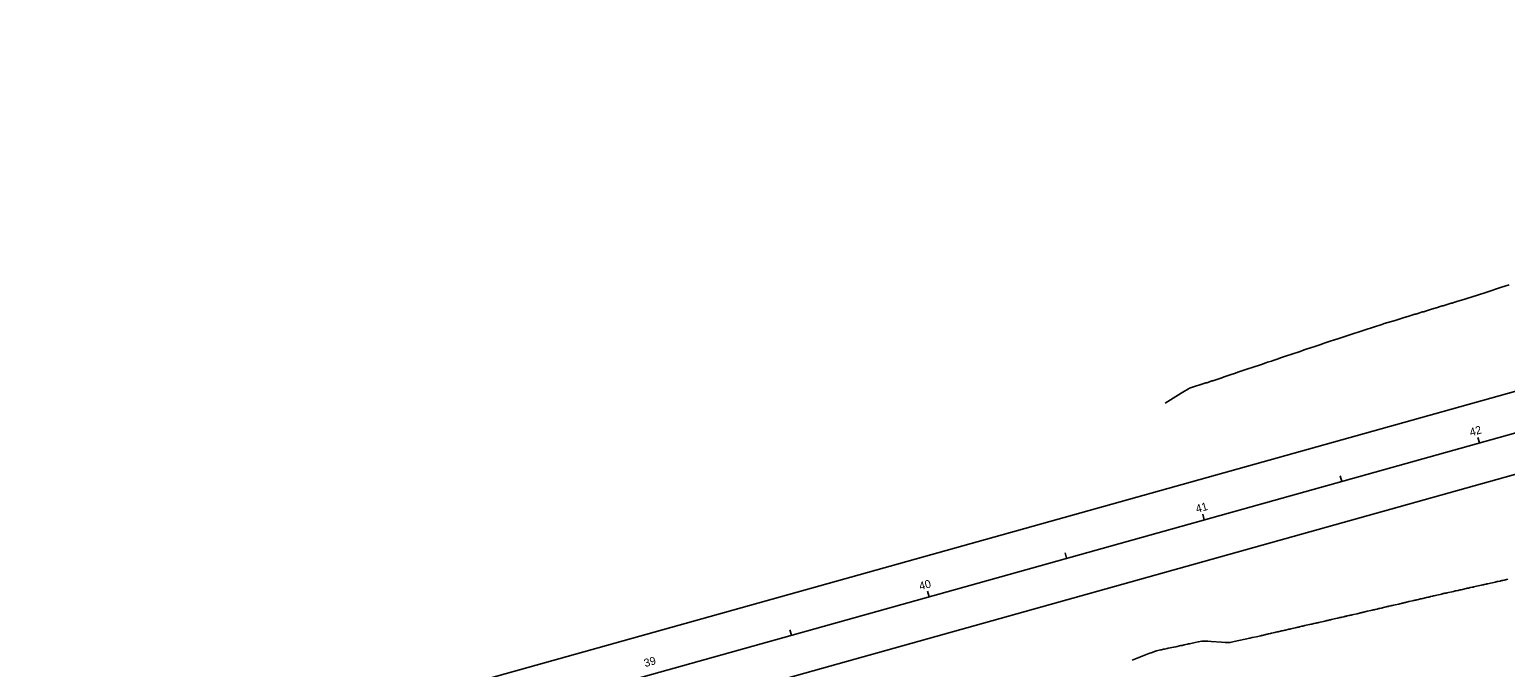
# Model space of a CAD drawing. Extents: x 1512289 to 1544686, y 552531 to 589211.
# Drawn here: x 1542314 to 1542831, y 587195 to 587419 of the extents above; entities that cross this region are included whole.
import ezdxf

# ---------------------------------------------------------------- set-up
doc = ezdxf.new("R2010")
doc.units = 0
for name, color, linetype in [('DR_X_Flood_Boundary', 7, 'Continuous'), ('DR_X_Underdrain', 7, 'Continuous'), ('GE_X_CL_20', 7, 'Continuous'), ('GK_Visualization', 7, 'Continuous')]:
    doc.layers.add(name, color=color, linetype=linetype)

msp = doc.modelspace()

# ---------------------------------------------------------------- linework, layer by layer
at = {"layer": 'DR_X_Flood_Boundary'}
for points in [[(1542711.77, 587287.84), (1542717.39, 587291.34), (1542718.47, 587292), (1542719.31, 587292.5), (1542719.91, 587292.83), (1542720.27, 587292.99), (1542726.04, 587294.85), (1542726.39, 587294.96), (1542726.71, 587295.07), (1542728.08, 587295.55), (1542728.4, 587295.66), (1542728.75, 587295.77), (1542730.52, 587296.35), (1542730.88, 587296.47), (1542731.23, 587296.59), (1542732.76, 587297.12), (1542733.11, 587297.24), (1542733.47, 587297.36), (1542735.26, 587297.94), (1542735.63, 587298.06), (1542735.97, 587298.18), (1542737.5, 587298.71), (1542737.84, 587298.83), (1542738.21, 587298.95), (1542740.01, 587299.53), (1542740.38, 587299.65), (1542740.72, 587299.77), (1542742.23, 587300.29), (1542742.58, 587300.41), (1542742.94, 587300.53), (1542744.76, 587301.12), (1542745.12, 587301.24), (1542745.47, 587301.36), (1542746.95, 587301.87), (1542747.56, 587302.08), (1542748.91, 587302.52), (1542749.52, 587302.72), (1542750.98, 587303.24), (1542751.33, 587303.35), (1542752.08, 587303.6), (1542753.54, 587304.07), (1542754.24, 587304.31), (1542755.71, 587304.82), (1542756.05, 587304.94), (1542756.81, 587305.19), (1542758.28, 587305.67), (1542758.98, 587305.9), (1542760.44, 587306.41), (1542761.15, 587306.65), (1542763.02, 587307.26), (1542763.73, 587307.49), (1542765.16, 587307.99), (1542765.88, 587308.23), (1542767.76, 587308.85), (1542768.47, 587309.08), (1542769.89, 587309.58), (1542770.61, 587309.82), (1542772.5, 587310.43), (1542773.21, 587310.67), (1542774.62, 587311.16), (1542775.33, 587311.4), (1542781.72, 587313.47), (1542787.57, 587315.37), (1542788.13, 587315.55), (1542788.4, 587315.63), (1542792.22, 587316.75), (1542792.6, 587316.87), (1542792.94, 587316.97), (1542793.24, 587317.07), (1542794.01, 587317.32), (1542794.31, 587317.41), (1542794.65, 587317.52), (1542795.03, 587317.63), (1542797.03, 587318.22), (1542797.41, 587318.34), (1542797.75, 587318.44), (1542798.05, 587318.54), (1542798.8, 587318.78), (1542799.1, 587318.87), (1542799.44, 587318.98), (1542799.82, 587319.09), (1542801.84, 587319.69), (1542802.22, 587319.8), (1542802.56, 587319.91), (1542802.85, 587320), (1542803.59, 587320.24), (1542803.88, 587320.33), (1542804.22, 587320.44), (1542804.61, 587320.55), (1542806.65, 587321.15), (1542807.03, 587321.27), (1542807.36, 587321.37), (1542807.66, 587321.46), (1542808.38, 587321.7), (1542808.67, 587321.79), (1542809.01, 587321.89), (1542809.4, 587322.01), (1542811.46, 587322.62), (1542811.84, 587322.73), (1542812.17, 587322.83), (1542812.46, 587322.92), (1542813.17, 587323.15), (1542813.46, 587323.25), (1542813.8, 587323.35), (1542814.18, 587323.46), (1542816.27, 587324.08), (1542816.65, 587324.19), (1542816.98, 587324.29), (1542817.27, 587324.38), (1542821.08, 587325.62), (1542824.33, 587326.67), (1542829.08, 587328.21), (1542832.15, 587329.2)], [(1542831.68, 587226.17), (1542830.42, 587225.89), (1542829.98, 587225.79), (1542829.59, 587225.7), (1542829.25, 587225.63), (1542828.96, 587225.56), (1542828.27, 587225.42), (1542827.98, 587225.35), (1542827.64, 587225.28), (1542827.25, 587225.19), (1542826.8, 587225.09), (1542825.55, 587224.8), (1542825.1, 587224.7), (1542824.71, 587224.62), (1542824.37, 587224.54), (1542824.08, 587224.48), (1542823.39, 587224.33), (1542823.1, 587224.27), (1542822.76, 587224.2), (1542822.37, 587224.11), (1542821.93, 587224.01), (1542820.67, 587223.72), (1542820.22, 587223.62), (1542819.83, 587223.53), (1542819.49, 587223.46), (1542819.21, 587223.39), (1542818.52, 587223.25), (1542818.23, 587223.19), (1542817.89, 587223.11), (1542817.5, 587223.02), (1542817.05, 587222.92), (1542815.79, 587222.64), (1542815.35, 587222.53), (1542814.96, 587222.45), (1542814.62, 587222.37), (1542814.33, 587222.31), (1542813.64, 587222.16), (1542813.35, 587222.1), (1542813.02, 587222.03), (1542812.62, 587221.94), (1542812.18, 587221.84), (1542810.92, 587221.55), (1542810.49, 587221.45), (1542810.14, 587221.37), (1542809.87, 587221.31), (1542809.68, 587221.27), (1542809.29, 587221.19), (1542809.1, 587221.15), (1542808.83, 587221.09), (1542808.48, 587221.01), (1542808.05, 587220.91), (1542806.78, 587220.62), (1542806.33, 587220.52), (1542805.94, 587220.43), (1542805.61, 587220.35), (1542805.32, 587220.28), (1542804.65, 587220.12), (1542804.36, 587220.06), (1542804.03, 587219.98), (1542803.64, 587219.89), (1542803.19, 587219.79), (1542801.92, 587219.5), (1542801.48, 587219.39), (1542801.08, 587219.3), (1542800.75, 587219.22), (1542800.46, 587219.16), (1542799.79, 587219), (1542799.5, 587218.93), (1542799.17, 587218.85), (1542798.77, 587218.76), (1542798.33, 587218.66), (1542797.06, 587218.37), (1542796.62, 587218.27), (1542796.22, 587218.18), (1542795.89, 587218.1), (1542795.61, 587218.03), (1542794.93, 587217.87), (1542794.64, 587217.8), (1542794.31, 587217.72), (1542793.91, 587217.63), (1542793.47, 587217.53), (1542792.2, 587217.24), (1542791.76, 587217.14), (1542791.37, 587217.05), (1542791.03, 587216.97), (1542790.75, 587216.9), (1542790.07, 587216.74), (1542789.78, 587216.68), (1542789.45, 587216.6), (1542789.05, 587216.51), (1542788.61, 587216.4), (1542787.34, 587216.12), (1542786.9, 587216.01), (1542786.51, 587215.92), (1542786.17, 587215.85), (1542785.89, 587215.78), (1542785.21, 587215.62), (1542784.92, 587215.55), (1542784.59, 587215.47), (1542784.19, 587215.38), (1542783.75, 587215.28), (1542782.49, 587214.99), (1542782.04, 587214.89), (1542781.65, 587214.8), (1542781.31, 587214.72), (1542781.03, 587214.65), (1542780.34, 587214.49), (1542780.06, 587214.42), (1542779.72, 587214.34), (1542779.33, 587214.25), (1542778.89, 587214.15), (1542777.63, 587213.86), (1542777.18, 587213.76), (1542776.79, 587213.67), (1542776.45, 587213.59), (1542776.17, 587213.52), (1542775.48, 587213.36), (1542775.26, 587213.31), (1542775.09, 587213.27), (1542774.97, 587213.24), (1542774.91, 587213.23), (1542774.84, 587213.21), (1542774.78, 587213.19), (1542774.66, 587213.17), (1542774.49, 587213.12), (1542774.25, 587213.07), (1542773.55, 587212.9), (1542773.27, 587212.83), (1542772.93, 587212.76), (1542772.54, 587212.67), (1542772.09, 587212.57), (1542770.85, 587212.3), (1542770.4, 587212.2), (1542770.01, 587212.11), (1542769.66, 587212.03), (1542769.37, 587211.96), (1542768.64, 587211.79), (1542768.34, 587211.72), (1542768, 587211.64), (1542767.61, 587211.55), (1542767.18, 587211.45), (1542765.96, 587211.18), (1542765.53, 587211.09), (1542765.14, 587211), (1542764.79, 587210.92), (1542764.48, 587210.85), (1542763.73, 587210.67), (1542763.42, 587210.59), (1542763.08, 587210.52), (1542762.69, 587210.43), (1542762.27, 587210.33), (1542761.08, 587210.07), (1542760.65, 587209.98), (1542760.26, 587209.89), (1542759.91, 587209.81), (1542759.6, 587209.73), (1542758.82, 587209.54), (1542758.51, 587209.47), (1542758.16, 587209.39), (1542757.78, 587209.3), (1542757.36, 587209.21), (1542756.19, 587208.95), (1542755.78, 587208.86), (1542755.39, 587208.77), (1542755.04, 587208.69), (1542754.72, 587208.62), (1542753.91, 587208.42), (1542753.59, 587208.35), (1542753.24, 587208.26), (1542752.86, 587208.18), (1542752.45, 587208.09), (1542751.31, 587207.84), (1542750.9, 587207.74), (1542750.52, 587207.66), (1542750.16, 587207.57), (1542749, 587207.3), (1542748.67, 587207.22), (1542747.94, 587207.05), (1542745.72, 587206.56), (1542745.47, 587206.5), (1542745.27, 587206.45), (1542744.65, 587206.3), (1542743.71, 587206.09), (1542742.22, 587205.76), (1542741.43, 587205.58), (1542735.93, 587204.36), (1542734.94, 587204.14), (1542734.45, 587204.08), (1542733.71, 587204.07), (1542732.72, 587204.1), (1542731.49, 587204.18), (1542727.88, 587204.45), (1542726.65, 587204.52), (1542725.69, 587204.56), (1542724.98, 587204.56), (1542724.53, 587204.51), (1542723.33, 587204.25), (1542722.2, 587204.01), (1542720.7, 587203.71), (1542720.31, 587203.63), (1542719.95, 587203.55), (1542719.61, 587203.48), (1542718.39, 587203.21), (1542718.03, 587203.14), (1542717.66, 587203.06), (1542717.27, 587202.98), (1542715.44, 587202.6), (1542714.73, 587202.45), (1542712.8, 587202.04), (1542712.46, 587201.96), (1542711.54, 587201.77), (1542711.2, 587201.69), (1542710.85, 587201.62), (1542710.51, 587201.54), (1542710.16, 587201.47), (1542709.23, 587201.27), (1542708.77, 587201.14), (1542708.08, 587200.92), (1542707.17, 587200.59), (1542706.04, 587200.16), (1542700.22, 587197.91)]]:
    msp.add_lwpolyline(points, dxfattribs=at)
at = {"layer": 'DR_X_Underdrain'}
for p, q in [((1543116.66, 587370.84), (1541208.48, 586837.66)), ((1543114.38, 587341.13), (1541216.02, 586810.7))]:
    msp.add_line(p, q, dxfattribs=at)
at = {"layer": 'GE_X_CL_20'}
for p, q in [((1541212.25, 586824.18), (1543339.29, 587418.51)), ((1542821.73, 587273.89), (1542821.19, 587275.82)), ((1542773.57, 587260.44), (1542773.04, 587262.36)), ((1542725.42, 587246.98), (1542724.88, 587248.91)), ((1542677.26, 587233.53), (1542676.72, 587235.45)), ((1542629.11, 587220.07), (1542628.57, 587222)), ((1542580.95, 587206.62), (1542580.41, 587208.54))]:
    msp.add_line(p, q, dxfattribs=at)
at = {"layer": 'GK_Visualization'}
msp.add_line((1541212.25, 586824.18), (1543339.29, 587418.51), dxfattribs=at)

# ---------------------------------------------------------------- texts
at = {"layer": 'GE_X_CL_20'}
for s, p in [('42', (1542818.73, 587276.17)), ('41', (1542722.87, 587249.39)), ('40', (1542626.05, 587222.33)), ('39', (1542529.78, 587195.43))]:
    msp.add_text(s, height=2.8, rotation=15.6111, dxfattribs=at).set_placement(p)

doc.saveas('drawing.dxf')
